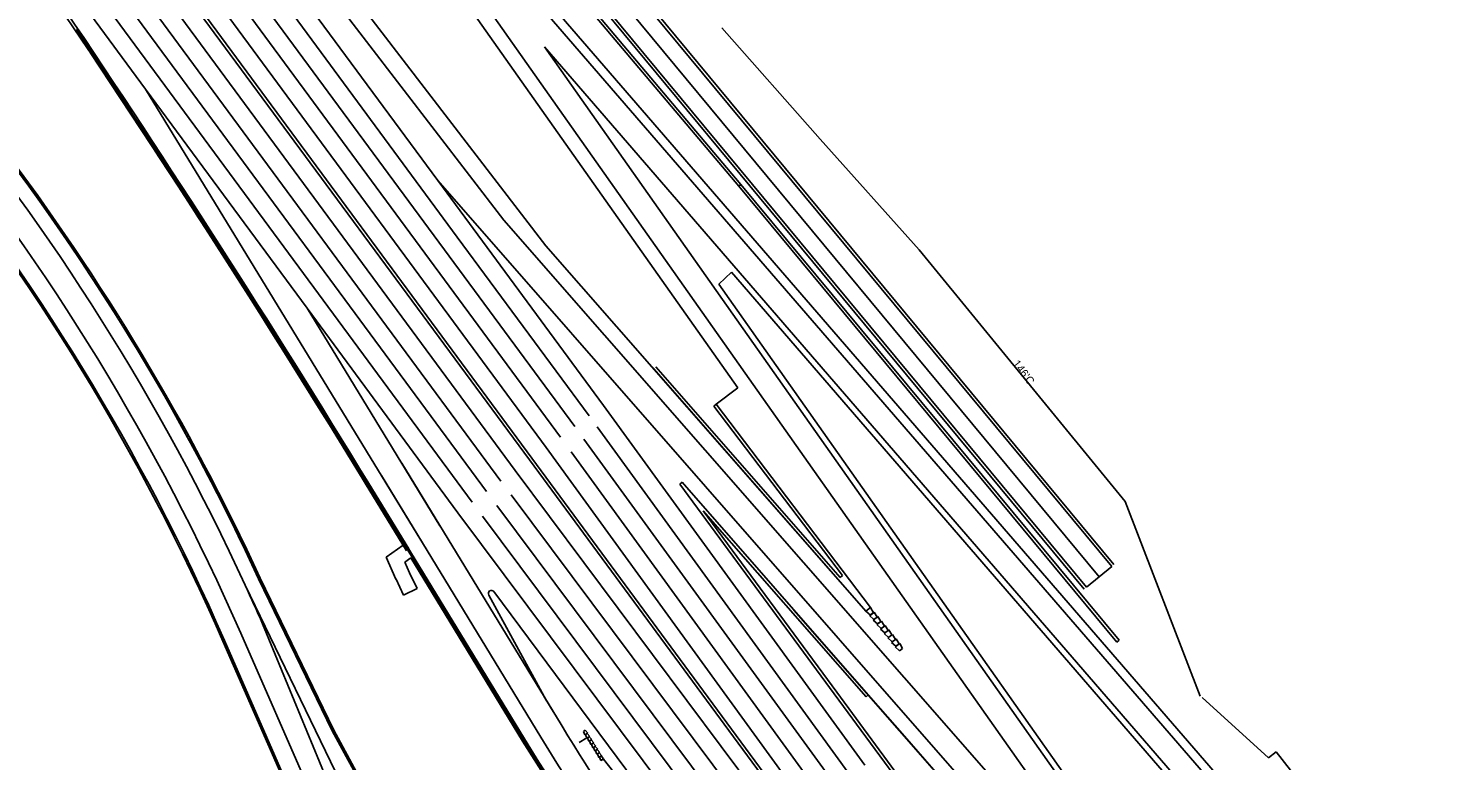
# Model space of a CAD drawing. Extents: x 1942118 to 1978871, y 789467 to 829913.
# Drawn here: x 1970148 to 1971104, y 796731 to 797225 of the extents above; entities that cross this region are included whole.
import ezdxf

# ---------------------------------------------------------------- set-up
doc = ezdxf.new("R2010")
doc.units = 0
for name, color, linetype in [('BR_CONCRETE', 7, 'Continuous'), ('RD_PD_ALT1_CL', 7, 'Continuous'), ('RD_PD_ALT1_TrvlWay', 7, 'Continuous'), ('RD_PD_CstnLmt', 7, 'Continuous'), ('RD_PD_Final_LnLine', 7, 'Continuous'), ('RD_PD_Final_TrvlWay', 7, 'Continuous'), ('RD_PD_GR', 7, 'Continuous'), ('RD_PD_MedBWall', 7, 'Continuous'), ('RD_PD_MedGR', 7, 'Continuous'), ('RD_PD_PaintMed', 7, 'Continuous'), ('RD_PD_PaveShd', 7, 'Continuous'), ('RD_PD_TX_CstnLmt', 7, 'Continuous'), ('RD_PD_WallFill', 7, 'Continuous')]:
    doc.layers.add(name, color=color, linetype=linetype)

msp = doc.modelspace()

# ---------------------------------------------------------------- linework, layer by layer
at = {"layer": 'BR_CONCRETE'}
for p, q in [((1970303.1, 796853.34), (1970352.74, 796750.86)), ((1970304.11, 796853.82), (1970353.74, 796751.38)), ((1970280.04, 796811.9), (1970359.59, 796630.15)), ((1970279.01, 796811.45), (1970358.56, 796629.7)), ((1970352.74, 796750.86), (1970407.29, 796650.86)), ((1970353.74, 796751.38), (1970408.31, 796651.35))]:
    msp.add_line(p, q, dxfattribs=at)
for radius, start, end in [(1520.88, 23.63926, 54.77615), (1522, 23.63926, 54.77615), (1560, 24.69395, 49.76906), (1561.13, 24.69436, 49.76906)]:
    msp.add_arc((1968885.76, 796201.61), radius, start, end, dxfattribs=at)
at = {"layer": 'RD_PD_ALT1_CL'}
for p, q in [((1970416.68, 797296.78), (1970931.78, 796566.41)), ((1970495.92, 797212.19), (1970951.01, 796686.05))]:
    msp.add_line(p, q, dxfattribs=at)
at = {"layer": 'RD_PD_ALT1_TrvlWay'}
for p, q in [((1970246.08, 797282.34), (1970497.04, 796941.91)), ((1970225.15, 797266.91), (1970476.11, 796926.49)), ((1970186.52, 797238.43), (1970226.81, 797183.77)), ((1970226.81, 797183.77), (1970412.48, 796879.57)), ((1970423.91, 797122.01), (1970535.68, 796970.4)), ((1970335.74, 797036.01), (1970425.4, 796889.1)), ((1970335.74, 797036.01), (1970437.48, 796898)), ((1970535.68, 796970.4), (1970712.08, 796727.74)), ((1970497.04, 796941.91), (1970673.45, 796699.25)), ((1970476.11, 796926.49), (1970655.74, 796686.2)), ((1970437.48, 796898), (1970617.1, 796657.72)), ((1970458.51, 796842.51), (1970497.13, 796771.59))]:
    msp.add_line(p, q, dxfattribs=at)
for centre, radius, start, end in [((1969481.96, 796626.87), 1150, 35.62905, 163.61097), ((1970460.12, 796843.69), 2, 36.39766, 216.39766)]:
    msp.add_arc(centre, radius, start, end, dxfattribs=at)
at = {"layer": 'RD_PD_CstnLmt'}
for p, q in [((1970615.52, 797225.13), (1970682.04, 797150.08)), ((1970189.41, 797208.37), (1970216.94, 797166.91)), ((1970216.94, 797166.91), (1970244.22, 797125.29)), ((1970682.04, 797150.08), (1970748.85, 797075.26)), ((1970244.22, 797125.29), (1970271.25, 797083.51)), ((1970271.25, 797083.51), (1970298.03, 797041.58)), ((1970748.85, 797075.26), (1970875.59, 796920.37)), ((1970298.03, 797041.58), (1970324.57, 796999.49)), ((1970324.57, 796999.49), (1970350.85, 796957.26)), ((1970400.54, 796876.09), (1970350.85, 796957.26)), ((1970875.59, 796920.37), (1970887.67, 796905.6)), ((1970887.67, 796905.6), (1970938.25, 796774.37)), ((1970400.54, 796876.09), (1970389.17, 796868)), ((1970395.75, 796853.3), (1970389.17, 796868)), ((1970405.76, 796867.54), (1970401.64, 796864.61)), ((1970404.88, 796857.39), (1970401.64, 796864.61)), ((1970405.76, 796867.54), (1970428.93, 796829.58)), ((1970395.81, 796853.18), (1970400.93, 796842.5)), ((1970404.82, 796857.51), (1970409.95, 796846.82)), ((1970400.93, 796842.5), (1970409.95, 796846.82)), ((1970428.93, 796829.58), (1970481.23, 796743.9)), ((1970939.71, 796773.37), (1970984.4, 796732.6)), ((1970481.23, 796743.9), (1970535, 796659.31)), ((1970989.68, 796736.67), (1970984.4, 796732.6)), ((1971004.79, 796717.1), (1970989.68, 796736.67))]:
    msp.add_line(p, q, dxfattribs=at)
at = {"layer": 'RD_PD_Final_LnLine'}
for p, q in [((1970284.69, 797310.85), (1970423.91, 797122.01)), ((1970275.06, 797303.7), (1970437.07, 797083.94)), ((1970265.4, 797296.58), (1970516.36, 796956.16)), ((1970255.74, 797289.46), (1970506.7, 796949.04)), ((1970205.84, 797252.67), (1970456.8, 796912.25)), ((1970215.49, 797259.79), (1970466.45, 796919.37)), ((1970196.18, 797245.55), (1970447.14, 796905.13)), ((1970226.81, 797183.77), (1970335.74, 797036.01)), ((1970437.07, 797083.94), (1970526.02, 796963.28)), ((1970531.4, 796955.87), (1970702.42, 796720.61)), ((1970522.56, 796947.63), (1970692.77, 796713.49)), ((1970514, 796938.99), (1970683.11, 796706.37)), ((1970473.38, 796910.1), (1970646.08, 796679.08)), ((1970463.77, 796902.92), (1970636.42, 796671.96)), ((1970454.15, 796895.74), (1970626.62, 796664.73)), ((1970376.6, 796651.49), (1970305.69, 796823.13))]:
    msp.add_line(p, q, dxfattribs=at)
msp.add_arc((1968885.76, 796201.61), 1550, 23.63926, 24.69023, dxfattribs=at)
at = {"layer": 'RD_PD_Final_TrvlWay'}
for p, q in [((1970379.89, 797463.11), (1970878.63, 796861.84)), ((1970362.95, 797449.06), (1970861.7, 796847.8)), ((1970349.66, 797405.75), (1970962.87, 796696.8)), ((1970468.57, 797095.3), (1970296.15, 797319.65)), ((1970495.92, 797212.19), (1970944.69, 796575.86)), ((1970423.91, 797122.01), (1971103.94, 796345.55)), ((1970468.57, 797095.3), (1970931.78, 796566.41)), ((1970399.62, 796931.35), (1970507.21, 796755.07)), ((1970385.96, 796923.02), (1970493.55, 796746.74)), ((1970878.63, 796861.84), (1970861.7, 796847.8)), ((1970294.05, 796849.07), (1970387.55, 796656.07)), ((1970458.51, 796842.51), (1970496.26, 796773.18)), ((1970461.73, 796844.88), (1970712.68, 796507.84)), ((1970291.03, 796816.71), (1970370.59, 796634.96))]:
    msp.add_line(p, q, dxfattribs=at)
for centre, radius, start, end in [((1968885.76, 796201.61), 1550, 24.69023, 54.77615), ((1968885.76, 796201.61), 1534, 23.63926, 54.77615), ((1970460.12, 796843.69), 2, 36.39766, 216.39766), ((1972641.14, 798057.51), 2500, 210.91274, 216.39766), ((1972641.14, 798057.51), 2516, 211.39766, 216.39766)]:
    msp.add_arc(centre, radius, start, end, dxfattribs=at)
at = {"layer": 'RD_PD_GR'}
for q in [(1970714.42, 796775.13), (1971033.24, 796411.1)]:
    msp.add_line((1970738.79, 796747.3), q, dxfattribs=at)
at = {"layer": 'RD_PD_MedBWall'}
for p, q in [((1970234.81, 797274.03), (1970485.77, 796933.61)), ((1970236.42, 797275.22), (1970487.38, 796934.79)), ((1970485.77, 796933.61), (1971046.58, 796172.88)), ((1970487.38, 796934.79), (1971048.19, 796174.06))]:
    msp.add_line(p, q, dxfattribs=at)
at = {"layer": 'RD_PD_MedGR'}
for p, q in [((1970716, 796834.03), (1970712.81, 796831.62)), ((1970712.81, 796831.62), (1970715.8, 796829.01)), ((1970718.46, 796831.01), (1970715.27, 796828.61)), ((1970715.8, 796829.01), (1970717.93, 796830.61)), ((1970717.93, 796830.61), (1970716, 796834.03)), ((1970720.39, 796827.6), (1970718.46, 796831.01)), ((1970715.27, 796828.61), (1970718.26, 796825.99)), ((1970720.92, 796828), (1970717.72, 796825.59)), ((1970717.72, 796825.59), (1970720.71, 796822.98)), ((1970718.26, 796825.99), (1970720.39, 796827.6)), ((1970723.38, 796824.99), (1970720.18, 796822.58)), ((1970720.18, 796822.58), (1970723.17, 796819.97)), ((1970720.71, 796822.98), (1970722.84, 796824.59)), ((1970722.84, 796824.59), (1970720.92, 796828)), ((1970725.84, 796821.97), (1970722.64, 796819.57)), ((1970723.17, 796819.97), (1970725.3, 796821.57)), ((1970725.3, 796821.57), (1970723.38, 796824.99)), ((1970727.76, 796818.56), (1970725.84, 796821.97)), ((1970722.64, 796819.57), (1970725.63, 796816.95)), ((1970724.24, 796820.77), (1970724.24, 796820.77)), ((1970728.29, 796818.96), (1970725.1, 796816.55)), ((1970725.1, 796816.55), (1970728.09, 796813.94)), ((1970725.63, 796816.95), (1970727.76, 796818.56)), ((1970730.75, 796815.95), (1970727.56, 796813.54)), ((1970727.56, 796813.54), (1970730.55, 796810.93)), ((1970728.09, 796813.94), (1970730.22, 796815.55)), ((1970730.22, 796815.55), (1970728.29, 796818.96)), ((1970733.21, 796812.93), (1970730.02, 796810.53)), ((1970730.55, 796810.93), (1970732.68, 796812.53)), ((1970732.68, 796812.53), (1970730.75, 796815.95)), ((1970735.14, 796809.52), (1970733.21, 796812.93)), ((1970730.02, 796810.53), (1970733.01, 796807.91)), ((1970735.67, 796809.92), (1970732.47, 796807.51)), ((1970732.47, 796807.51), (1970735.47, 796804.9)), ((1970733.01, 796807.91), (1970735.14, 796809.52)), ((1970735.47, 796804.9), (1970737.6, 796806.51)), ((1970737.6, 796806.51), (1970735.67, 796809.92)), ((1970523.46, 796751.31), (1970522.22, 796750.55)), ((1970522.22, 796750.55), (1970523.25, 796748.18)), ((1970523.25, 796748.18), (1970525.12, 796749.33)), ((1970525.12, 796749.33), (1970523.46, 796751.31)), ((1970524.81, 796749.14), (1970523.57, 796748.37)), ((1970523.57, 796748.37), (1970524.6, 796746.01)), ((1970524.6, 796746.01), (1970526.46, 796747.16)), ((1970526.46, 796747.16), (1970524.81, 796749.14)), ((1970526.15, 796746.97), (1970524.91, 796746.2)), ((1970524.91, 796746.2), (1970525.95, 796743.84)), ((1970525.95, 796743.84), (1970527.81, 796744.99)), ((1970527.81, 796744.99), (1970526.15, 796746.97)), ((1970527.5, 796744.8), (1970526.26, 796744.03)), ((1970529.15, 796742.82), (1970527.5, 796744.8)), ((1970526.26, 796744.03), (1970527.29, 796741.66)), ((1970527.29, 796741.66), (1970529.15, 796742.82)), ((1970528.84, 796742.63), (1970527.6, 796741.86)), ((1970527.6, 796741.86), (1970528.64, 796739.49)), ((1970528.64, 796739.49), (1970530.5, 796740.64)), ((1970530.5, 796740.64), (1970528.84, 796742.63)), ((1970530.19, 796740.45), (1970528.95, 796739.68)), ((1970528.95, 796739.68), (1970529.98, 796737.32)), ((1970529.57, 796740.07), (1970529.57, 796740.07)), ((1970529.98, 796737.32), (1970531.85, 796738.47)), ((1970531.85, 796738.47), (1970530.19, 796740.45)), ((1970531.54, 796738.28), (1970530.29, 796737.51)), ((1970530.29, 796737.51), (1970531.33, 796735.15)), ((1970531.33, 796735.15), (1970533.19, 796736.3)), ((1970533.19, 796736.3), (1970531.54, 796738.28)), ((1970532.88, 796736.11), (1970531.64, 796735.34)), ((1970531.64, 796735.34), (1970532.68, 796732.97)), ((1970534.54, 796734.13), (1970532.88, 796736.11)), ((1970532.68, 796732.97), (1970534.54, 796734.13)), ((1970534.23, 796733.94), (1970532.99, 796733.17)), ((1970532.99, 796733.17), (1970534.02, 796730.8)), ((1970534.02, 796730.8), (1970535.88, 796731.96)), ((1970535.88, 796731.96), (1970534.23, 796733.94))]:
    msp.add_line(p, q, dxfattribs=at)
at = {"layer": 'RD_PD_PaintMed'}
msp.add_line((1970371.42, 797456.09), (1970870.17, 796854.82), dxfattribs=at)
at = {"layer": 'RD_PD_PaveShd'}
for p, q in [((1970381.42, 797464.39), (1970880.17, 796863.12)), ((1970361.41, 797447.79), (1970860.16, 796846.52)), ((1970354.19, 797409.67), (1970967.4, 796700.73)), ((1970496.9, 797078.14), (1970305.44, 797327.25)), ((1970418.57, 797276.75), (1970626.31, 796982.2)), ((1970496.9, 797078.14), (1970712.9, 796831.5)), ((1970622.02, 797060.28), (1970613.59, 797052.28)), ((1970622.02, 797060.28), (1970948.04, 796683.37)), ((1970613.59, 797052.28), (1970915.2, 796624.62)), ((1970626.31, 796982.2), (1970611.83, 796971.2)), ((1970611.83, 796971.2), (1970715.91, 796834.14)), ((1970485.77, 796933.61), (1971046.58, 796172.88)), ((1970487.38, 796934.79), (1971048.19, 796174.06)), ((1970377.42, 796917.81), (1970485.02, 796741.53)), ((1970587.2, 796917.36), (1970588.81, 796918.54)), ((1970587.2, 796917.36), (1970691.5, 796775.88)), ((1970714.42, 796775.13), (1970588.81, 796918.54)), ((1970303.1, 796853.34), (1970352.74, 796750.86)), ((1970664.28, 796832.37), (1971096.42, 796338.96)), ((1970280.04, 796811.9), (1970359.59, 796630.15)), ((1970691.5, 796775.88), (1971027.63, 796319.93)), ((1970352.74, 796750.86), (1970407.29, 796650.86)), ((1970524.45, 796746.13), (1970519.35, 796742.97)), ((1970534.02, 796730.8), (1970535.72, 796731.87)), ((1970535.72, 796731.87), (1970712.68, 796507.84))]:
    msp.add_line(p, q, dxfattribs=at)
for centre, radius, start, end in [((1968885.76, 796201.61), 1560, 24.69432, 54.77615), ((1968885.76, 796201.61), 1522, 23.63926, 54.77615), ((1972641.14, 798057.51), 2526, 211.39766, 216.39766)]:
    msp.add_arc(centre, radius, start, end, dxfattribs=at)
at = {"layer": 'RD_PD_WallFill'}
for p, q in [((1970626.99, 797118.22), (1970399.23, 797388.09)), ((1970400.74, 797389.41), (1970628.53, 797119.5)), ((1970181.14, 797224.32), (1970180.31, 797223.76)), ((1970628.53, 797119.5), (1970626.99, 797118.22)), ((1970626.99, 797118.22), (1970882.06, 796810.72)), ((1970628.53, 797119.5), (1970883.6, 796812)), ((1970569.45, 796995.29), (1970712.9, 796831.5)), ((1970571.06, 796996.48), (1970695.51, 796854.39)), ((1970611.83, 796971.2), (1970610.24, 796969.99)), ((1970610.24, 796969.99), (1970697.07, 796855.65)), ((1970611.83, 796971.2), (1970715.91, 796834.14)), ((1970375.72, 796916.77), (1970402.78, 796872.43)), ((1970376.57, 796917.29), (1970484.16, 796741.01)), ((1970377.42, 796917.81), (1970404.4, 796873.62)), ((1970377.42, 796917.81), (1970485.02, 796741.53)), ((1970587.2, 796917.36), (1970588.81, 796918.54)), ((1970587.2, 796917.36), (1970691.5, 796775.88)), ((1970588.81, 796918.54), (1970714.42, 796775.13)), ((1970602.95, 796899.36), (1970693.11, 796777.07)), ((1970602.95, 796899.36), (1970712.91, 796773.81)), ((1970695.51, 796854.39), (1970697.07, 796855.65)), ((1970715.91, 796834.14), (1970712.9, 796831.5)), ((1970882.06, 796810.72), (1970883.6, 796812)), ((1970691.5, 796775.88), (1971027.63, 796319.93)), ((1970693.11, 796777.07), (1971029.24, 796321.12)), ((1970714.42, 796775.13), (1970712.91, 796773.81)), ((1970534.02, 796730.8), (1970535.71, 796731.87)), ((1970535.72, 796731.87), (1970712.68, 796507.84))]:
    msp.add_line(p, q, dxfattribs=at)
for centre, radius, start, end in [((1963181.81, 792525.99), 8428, 31.397656, 33.979468), ((1963181.81, 792525.99), 8430, 31.397656, 33.979468), ((1963181.81, 792525.99), 8429, 31.397656, 33.871644), ((1972641.14, 798057.51), 2527, 211.39766, 216.39766), ((1972641.14, 798057.51), 2526, 211.39766, 216.39766)]:
    msp.add_arc(centre, radius, start, end, dxfattribs=at)

# ---------------------------------------------------------------- texts
at = {"layer": 'RD_PD_TX_CstnLmt'}
msp.add_text("146'C", height=5.4, rotation=307.21202, dxfattribs=at).set_placement((1970811.46, 796998.51))

doc.saveas('drawing.dxf')
